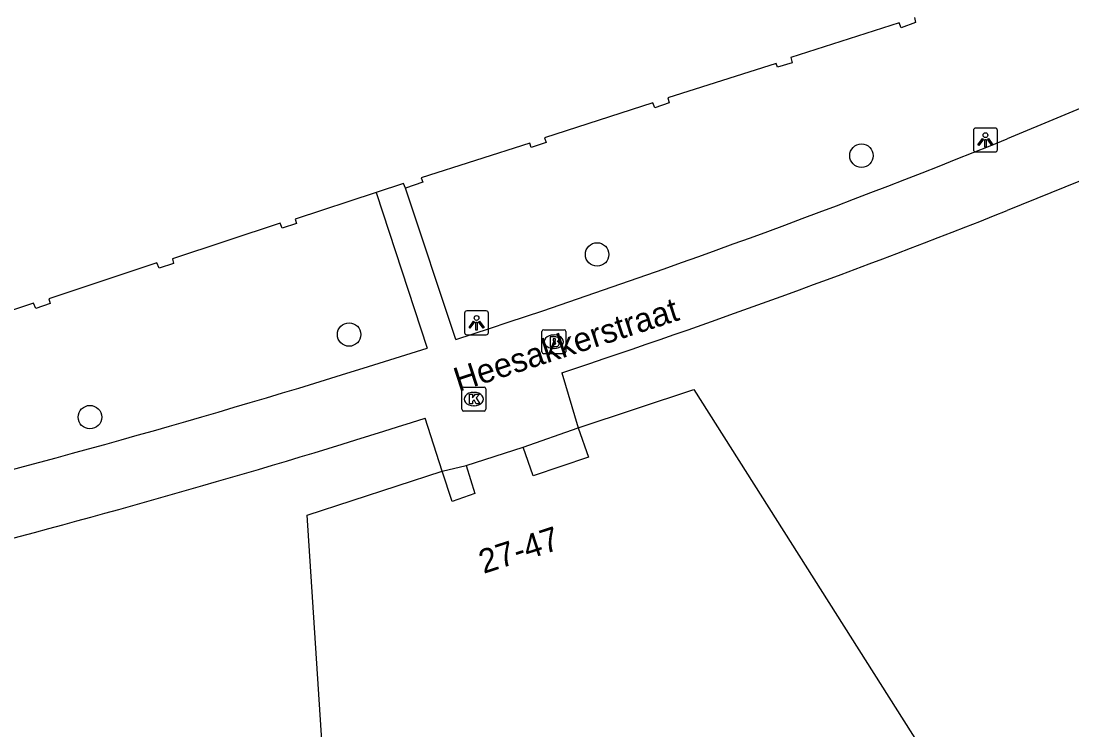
# Model space of a CAD drawing. Extents: x 159265 to 160143, y 383413 to 384319.
# Drawn here: x 159458.88 to 159502.7, y 383956.89 to 383986.45 of the extents above; entities that cross this region are included whole.
import ezdxf

# ---------------------------------------------------------------- set-up
doc = ezdxf.new("R2010")
doc.units = 0
for name, color, linetype in [('IMGEO_Boom', 7, 'Continuous'), ('IMGEO_Brandkraan', 7, 'Continuous'), ('IMGEO_Kolk', 7, 'Continuous'), ('IMGEO_Lichtpunt', 7, 'Continuous'), ('IMGEO_Openbare_ruimte_label', 7, 'Continuous'), ('IMGEO_Pand', 7, 'Continuous'), ('IMGEO_Pand_nummerreeks', 7, 'Continuous'), ('IMGEO_Voetpad_open', 7, 'Continuous')]:
    doc.layers.add(name, color=color, linetype=linetype)

msp = doc.modelspace()

# ---------------------------------------------------------------- linework, layer by layer
at = {"layer": 'IMGEO_Boom'}
for centre in [(159493.922, 383980.836), (159482.9, 383976.718), (159472.56, 383973.38), (159461.756, 383969.935)]:
    msp.add_circle(centre, 0.489, dxfattribs=at)
at = {"layer": 'IMGEO_Brandkraan'}
for p, q in [((159480.6, 383972.654), (159480.6, 383973.506)), ((159480.675, 383973.58), (159481.527, 383973.58)), ((159481.601, 383973.506), (159481.601, 383972.654)), ((159481.088, 383973.36), (159481.113, 383973.36)), ((159481.111, 383972.8), (159481.086, 383972.8)), ((159481.527, 383972.58), (159480.675, 383972.58))]:
    msp.add_line(p, q, dxfattribs=at)
for points in [[(159480.6, 383972.654), (159480.6, 383973.506)], [(159480.675, 383973.58), (159481.527, 383973.58)], [(159481.601, 383973.506), (159481.601, 383972.654)], [(159480.948, 383973.28), (159480.948, 383972.88), (159481.161, 383972.88)], [(159481.179, 383973.28), (159480.948, 383973.28)], [(159481.127, 383973.199), (159481.073, 383973.199), (159481.073, 383973.123)], [(159481.073, 383973.123), (159481.126, 383973.123)], [(159481.135, 383973.047), (159481.073, 383973.047), (159481.073, 383972.966)], [(159481.073, 383972.966), (159481.135, 383972.966)], [(159481.527, 383972.58), (159480.675, 383972.58)]]:
    msp.add_lwpolyline(points, dxfattribs=at)
for centre, radius, start, end in [((159480.677, 383973.504), 0.0765, 91.552, 178.448), ((159480.677, 383973.504), 0.0765, 91.552, 178.448), ((159481.525, 383973.504), 0.0765, 1.552, 88.448), ((159481.525, 383973.504), 0.0765, 1.552, 88.448), ((159481.128, 383973.161), 0.0379, 267.8285, 90.9355), ((159481.183, 383973.135), 0.145, 59.4692, 91.5367), ((159481.208, 383973.182), 0.0922, 285.5137, 58.1501), ((159481.213, 383972.99), 0.105, 301.3115, 78.989), ((159480.677, 383972.656), 0.0765, 181.552, 268.448), ((159480.677, 383972.656), 0.0765, 181.552, 268.448), ((159481.136, 383973.006), 0.0404, 269.8759, 90.5077), ((159481.167, 383973.131), 0.251, 268.6676, 293.5347), ((159481.525, 383972.656), 0.0765, 271.552, 358.448), ((159481.525, 383972.656), 0.0765, 271.552, 358.448)]:
    msp.add_arc(centre, radius, start, end, dxfattribs=at)
for centre, major_axis, ratio, start_param, end_param in [((159481.087, 383973.08), (-0.387, 0.002), 0.722429, 4.712389, 7.853982), ((159481.112, 383973.08), (-0.39, 0.002), 0.717154, 1.570796, 4.712389)]:
    msp.add_ellipse(centre, major_axis=major_axis, ratio=ratio, start_param=start_param, end_param=end_param, dxfattribs=at)
at = {"layer": 'IMGEO_Kolk'}
for p, q in [((159477.261, 383970.261), (159477.261, 383971.113)), ((159477.336, 383971.187), (159478.188, 383971.187)), ((159477.749, 383970.967), (159477.774, 383970.967)), ((159478.262, 383971.113), (159478.262, 383970.261)), ((159478.188, 383970.187), (159477.336, 383970.187)), ((159477.772, 383970.407), (159477.747, 383970.407))]:
    msp.add_line(p, q, dxfattribs=at)
for points in [[(159477.261, 383970.261), (159477.261, 383971.113)], [(159477.336, 383971.187), (159478.188, 383971.187)], [(159477.582, 383970.887), (159477.705, 383970.887), (159477.705, 383970.736), (159477.835, 383970.887), (159477.999, 383970.887), (159477.853, 383970.736), (159478.006, 383970.487), (159477.854, 383970.487), (159477.769, 383970.651), (159477.705, 383970.584), (159477.705, 383970.487), (159477.582, 383970.487), (159477.582, 383970.887)], [(159478.262, 383971.113), (159478.262, 383970.261)], [(159478.188, 383970.187), (159477.336, 383970.187)]]:
    msp.add_lwpolyline(points, dxfattribs=at)
for centre, start, end in [((159477.338, 383971.111), 91.552, 178.448), ((159477.338, 383971.111), 91.552, 178.448), ((159478.186, 383971.111), 1.552, 88.448), ((159478.186, 383971.111), 1.552, 88.448), ((159477.338, 383970.263), 181.552, 268.448), ((159477.338, 383970.263), 181.552, 268.448), ((159478.186, 383970.263), 271.552, 358.448), ((159478.186, 383970.263), 271.552, 358.448)]:
    msp.add_arc(centre, 0.0765, start, end, dxfattribs=at)
for centre, major_axis, ratio, start_param, end_param in [((159477.748, 383970.687), (-0.387, 0.002), 0.722429, 4.712389, 7.853982), ((159477.773, 383970.687), (-0.39, 0.002), 0.717154, 1.570796, 4.712389)]:
    msp.add_ellipse(centre, major_axis=major_axis, ratio=ratio, start_param=start_param, end_param=end_param, dxfattribs=at)
at = {"layer": 'IMGEO_Lichtpunt'}
for p, q in [((159498.592, 383981.892), (159498.592, 383981.085)), ((159498.592, 383981.892), (159498.592, 383981.085)), ((159499.494, 383981.987), (159498.686, 383981.987)), ((159499.494, 383981.987), (159498.686, 383981.987)), ((159499.588, 383981.085), (159499.588, 383981.892)), ((159499.588, 383981.085), (159499.588, 383981.892)), ((159498.686, 383980.991), (159499.494, 383980.991)), ((159498.686, 383980.991), (159499.494, 383980.991)), ((159477.375, 383974.272), (159477.375, 383973.465)), ((159477.375, 383974.272), (159477.375, 383973.465)), ((159478.277, 383974.367), (159477.469, 383974.367)), ((159478.277, 383974.367), (159477.469, 383974.367)), ((159478.371, 383973.465), (159478.371, 383974.272)), ((159478.371, 383973.465), (159478.371, 383974.272)), ((159477.469, 383973.371), (159478.277, 383973.371)), ((159477.469, 383973.371), (159478.277, 383973.371))]:
    msp.add_line(p, q, dxfattribs=at)
for points in [[(159498.966, 383981.556), (159499.005, 383981.528), (159498.817, 383981.266), (159498.779, 383981.293), (159498.966, 383981.556)], [(159499.068, 383981.508), (159499.115, 383981.508), (159499.115, 383981.186), (159499.068, 383981.186), (159499.068, 383981.508)], [(159499.178, 383981.528), (159499.216, 383981.555), (159499.403, 383981.293), (159499.364, 383981.265), (159499.178, 383981.528)], [(159477.749, 383973.936), (159477.788, 383973.908), (159477.6, 383973.646), (159477.562, 383973.673), (159477.749, 383973.936)], [(159477.851, 383973.888), (159477.898, 383973.888), (159477.898, 383973.566), (159477.851, 383973.566), (159477.851, 383973.888)], [(159477.961, 383973.908), (159477.999, 383973.935), (159478.186, 383973.673), (159478.147, 383973.645), (159477.961, 383973.908)]]:
    msp.add_lwpolyline(points, dxfattribs=at)
for centre in [(159499.091, 383981.69), (159477.874, 383974.07)]:
    msp.add_circle(centre, 0.0994, dxfattribs=at)
for centre, start, end in [((159498.686, 383981.892), 90, 180), ((159498.686, 383981.892), 90, 180), ((159499.494, 383981.892), 0, 90), ((159499.494, 383981.892), 0, 90), ((159498.686, 383981.085), 180, 270), ((159498.686, 383981.085), 180, 270), ((159499.494, 383981.085), 270, 0), ((159499.494, 383981.085), 270, 360), ((159477.469, 383974.272), 90, 180), ((159477.469, 383974.272), 90, 180), ((159478.277, 383974.272), 0, 90), ((159478.277, 383974.272), 0, 90), ((159477.469, 383973.465), 180, 270), ((159477.469, 383973.465), 180, 270), ((159478.277, 383973.465), 270, 0), ((159478.277, 383973.465), 270, 360)]:
    msp.add_arc(centre, 0.0946, start, end, dxfattribs=at)
at = {"layer": 'IMGEO_Pand'}
for points in [[(159496.135, 383986.59), (159496.17, 383986.383), (159495.575, 383986.162), (159495.498, 383986.37), (159490.984, 383984.923), (159491.03, 383984.711), (159490.426, 383984.521), (159490.367, 383984.684), (159485.849, 383983.247), (159485.907, 383983.042), (159485.308, 383982.83), (159485.224, 383983.041), (159480.708, 383981.58), (159480.777, 383981.383), (159480.145, 383981.175), (159480.098, 383981.351), (159475.566, 383979.918), (159475.634, 383979.73), (159474.907, 383979.484)], [(159474.907, 383979.484), (159474.824, 383979.669), (159473.695, 383979.298)], [(159473.695, 383979.298), (159470.318, 383978.188), (159470.373, 383978.009), (159469.77, 383977.812), (159469.69, 383978.016), (159465.191, 383976.542), (159465.245, 383976.342), (159464.635, 383976.146), (159464.539, 383976.369), (159460.048, 383974.863), (159460.099, 383974.667), (159459.493, 383974.467), (159459.403, 383974.682), (159454.921, 383973.2)], [(159482.115, 383969.493), (159486.934, 383971.093), (159496.316, 383956.284)], [(159482.115, 383969.493), (159482.544, 383968.266), (159480.232, 383967.495), (159479.82, 383968.683)], [(159477.446, 383967.917), (159479.82, 383968.683)], [(159477.446, 383967.917), (159477.8, 383966.75), (159476.854, 383966.419), (159476.434, 383967.682)], [(159471.946, 383948.349), (159470.816, 383965.847), (159476.434, 383967.682)]]:
    msp.add_lwpolyline(points, dxfattribs=at)
at = {"layer": 'IMGEO_Voetpad_open'}
for points in [[(159518.095, 383984.323), (159517.519, 383986.082), (159507.775, 383981.75), (159503.64, 383980.018), (159500, 383978.55)], [(159506.714, 383984.332), (159500, 383981.537)], [(159473.695, 383979.298), (159475.818, 383972.813)], [(159477.007, 383973.173), (159474.907, 383979.484)], [(159481.431, 383971.787), (159482.115, 383969.493)], [(159476.434, 383967.682), (159475.738, 383969.889)], [(159479.82, 383968.683), (159482.115, 383969.493)], [(159476.434, 383967.682), (159477.446, 383967.917)]]:
    msp.add_lwpolyline(points, dxfattribs=at)
for centre, radius, start, end in [((159369.015, 384305.833), 349.75, 287.98501, 291.994), ((159373.892, 384295.928), 341.514, 288.3541, 291.67007), ((159361.701, 384330.59), 375.535, 280.84144, 287.69069), ((159363.187, 384324.991), 372.512, 281.6203, 287.58626)]:
    msp.add_arc(centre, radius, start, end, dxfattribs=at)

# ---------------------------------------------------------------- texts
at = {"layer": 'IMGEO_Openbare_ruimte_label'}
msp.add_text('Heesakkerstraat', height=1, rotation=18.0001, dxfattribs=at).set_placement((159477.125, 383970.986))
at = {"layer": 'IMGEO_Pand_nummerreeks'}
msp.add_text('27-47', height=1, rotation=17.9837, dxfattribs=at).set_placement((159478.166, 383963.396))

doc.saveas('drawing.dxf')
